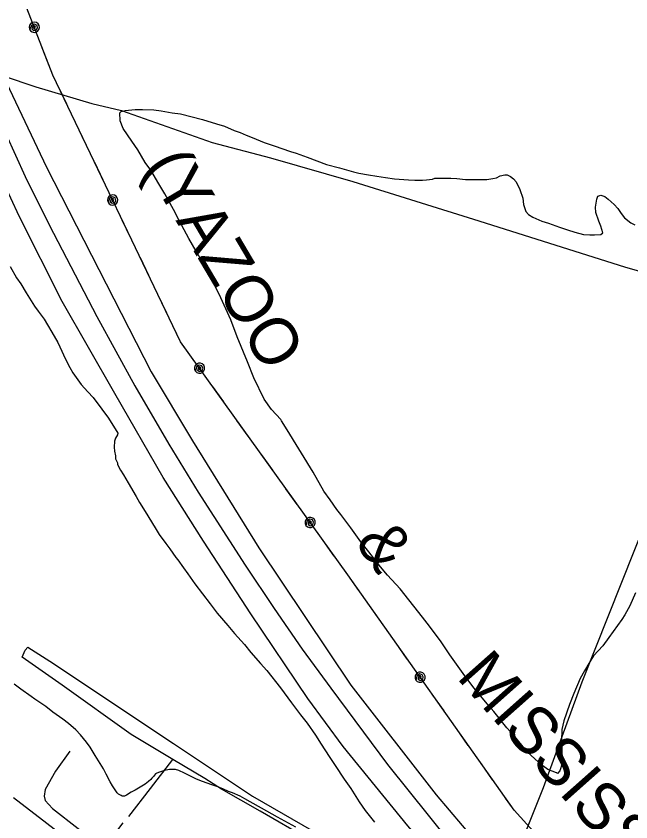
# Model space of a CAD drawing. Extents: x 3324104 to 3361979, y 612876 to 638273.
# Drawn here: x 3356671 to 3357754, y 633497 to 634915 of the extents above; entities that cross this region are included whole.
import ezdxf

# ---------------------------------------------------------------- set-up
doc = ezdxf.new("R2010")
doc.units = 0
for name, color, linetype in [('V-RAIL-IDEN', 7, 'Continuous'), ('V-RAIL-TRAK', 7, 'Continuous'), ('V-ROAD-CNTR', 7, 'Continuous'), ('V-SITE-VEGE', 7, 'Continuous'), ('V-TOPO-SHOR', 7, 'Continuous'), ('V-UTIL-LINE', 7, 'Continuous')]:
    doc.layers.add(name, color=color, linetype=linetype)

msp = doc.modelspace()

# ---------------------------------------------------------------- linework, layer by layer
at = {"layer": 'V-RAIL-TRAK'}
msp.add_lwpolyline([(3356215.6, 635761.2), (3356284.7, 635591.1), (3356397, 635315.7), (3356492.2, 635083.5), (3356560, 634919.7), (3356618.9, 634783), (3356687.5, 634633.1), (3356729.4, 634548), (3356813.2, 634386.8), (3356880.5, 634264.7), (3356940.4, 634162), (3356992, 634077.6), (3357074.6, 633949.1), (3357125.6, 633873), (3357175.2, 633801), (3357225.5, 633732.6), (3357325.5, 633598.4), (3357435.2, 633461.4), (3357535.9, 633341.2), (3357622.9, 633243.9), (3357692.7, 633167.7), (3357745.2, 633112.4), (3357828.1, 633029.8)], dxfattribs=at)
at = {"layer": 'V-ROAD-CNTR'}
msp.add_lwpolyline([(3356667, 633540.2), (3356968.1, 633308.6)], dxfattribs=at)
at = {"layer": 'V-SITE-VEGE'}
for points in [[(3356875, 634695.4), (3356860.1, 634717.2), (3356854.5, 634731.2), (3356854.1, 634745.2), (3356856.2, 634747.2), (3356863.4, 634749.3), (3356881, 634750.7), (3356893.9, 634750.6), (3356914.1, 634750), (3356926.5, 634748.3), (3356946.1, 634745.1), (3356960.6, 634743.5), (3356999.3, 634733.4), (3357024, 634725.5), (3357038, 634721.3), (3357055.5, 634713.9), (3357065.8, 634710.2), (3357076.1, 634706), (3357087, 634701.8), (3357108.1, 634692.9), (3357125.6, 634687.1), (3357154.5, 634677.1), (3357164.3, 634673.9), (3357183.9, 634667.1), (3357218, 634653.9), (3357240.7, 634648.1), (3357265.4, 634641.2), (3357274.7, 634639.1), (3357291.8, 634635.9), (3357306.2, 634633.7), (3357321.7, 634631.1), (3357337.7, 634628.9), (3357362, 634627.2), (3357373.4, 634626.6), (3357386.8, 634626.5), (3357394.1, 634627), (3357404.4, 634628.5), (3357408.6, 634630), (3357437, 634629.8), (3357447.3, 634629.2), (3357462.8, 634627.6), (3357492.8, 634627.4), (3357500, 634627.8), (3357510.4, 634629.3), (3357517.1, 634630.8), (3357523.4, 634633.9), (3357531.6, 634635.9), (3357535.8, 634635.9), (3357542, 634632.7), (3357547.1, 634629.1), (3357551.7, 634623.4), (3357558.4, 634609.9), (3357563.4, 634594.9), (3357564.9, 634583.5), (3357569, 634571.1), (3357573.6, 634565.9), (3357581.3, 634561.7), (3357596.8, 634554.3), (3357608.6, 634550.6), (3357628.2, 634543.8), (3357642.2, 634539.1), (3357655.1, 634534.8), (3357670, 634531.1), (3357681.4, 634530.5), (3357689.7, 634530.5), (3357700.5, 634530.9), (3357704.2, 634534), (3357702.6, 634539.7), (3357700.6, 634545.4), (3357697.1, 634554.2), (3357692, 634569.8), (3357691.5, 634579.1), (3357693.7, 634593), (3357695.8, 634598.2), (3357700.5, 634600.2), (3357707.7, 634597.6), (3357713.8, 634592.9), (3357724.1, 634583.5), (3357730.8, 634576.7), (3357736.4, 634567.9), (3357742.6, 634560.1), (3357753.4, 634551.3), (3357760.6, 634548.1)], [(3357761.6, 633900.4), (3357751.7, 633877.7), (3357742.8, 633861.7), (3357737.5, 633853.5), (3357714.6, 633821.6), (3357704.2, 633807.2), (3357688, 633789.7), (3357681.2, 633778.9), (3357671.8, 633762.9), (3357664.5, 633749.5), (3357653.5, 633723.2), (3357645.6, 633703.6), (3357635.6, 633675.3), (3357631.9, 633659.8), (3357631.8, 633640.1), (3357632.2, 633626.2), (3357632.6, 633605.5), (3357632.5, 633599.8), (3357628.8, 633586.9), (3357624.7, 633582.3), (3357622.6, 633583.3), (3357607.7, 633589.6), (3357598.9, 633595.9), (3357591.2, 633602.1), (3357577.3, 633614.6), (3357566.5, 633626.6), (3357549.1, 633647.4), (3357535.2, 633662.5), (3357512.7, 633691.6), (3357503.9, 633701.4), (3357477.8, 633732.6), (3357461.4, 633754.4), (3357435.2, 633791.3), (3357418.3, 633815.7), (3357394.8, 633846.9), (3357387.1, 633857.3), (3357347.6, 633907.1), (3357325.5, 633931.6), (3357312.7, 633946.1), (3357292.2, 633972.6), (3357278.3, 633990.3), (3357260.4, 634014.7), (3357255.3, 634021.5), (3357243, 634038.1), (3357235.8, 634046.9), (3357224, 634064.1), (3357213.2, 634079.1), (3357194.3, 634112.8), (3357148.3, 634187.1), (3357138.6, 634203.2), (3357137.5, 634205.2), (3357121.1, 634222.9), (3357108.3, 634241.1), (3357089.9, 634278.4), (3357078.7, 634306.9), (3357060.4, 634351), (3357049.2, 634380.5), (3357031.9, 634419.4), (3357019.7, 634444.8), (3357007.9, 634467.6), (3356988.5, 634501.4), (3356975.2, 634523.7), (3356958.8, 634554.3), (3356948.6, 634575), (3356933.3, 634602.5), (3356922.6, 634620.2), (3356908.8, 634644), (3356898.5, 634657.5), (3356885.7, 634679.9), (3356875, 634695.4)], [(3356661.1, 634474.5), (3356672.3, 634454.8), (3356679.5, 634443.9), (3356689.2, 634428.3), (3356694.8, 634419)], [(3356694.8, 634419), (3356703.5, 634405), (3356710.2, 634396.1), (3356720.5, 634382.1), (3356726.6, 634371.7), (3356734.3, 634359.3), (3356745, 634340.6), (3356751.6, 634325.6), (3356757.7, 634312.6), (3356765.9, 634297), (3356771.5, 634287.7), (3356780.3, 634275.2), (3356785.9, 634266.9), (3356797.7, 634253.9), (3356806.9, 634244), (3356822.3, 634223.8), (3356834.1, 634207.7), (3356850.5, 634181.2), (3356849.9, 634178.6), (3356846.3, 634172.5), (3356844.7, 634167.3), (3356844.1, 634156.4), (3356844.6, 634149.7), (3356846.1, 634141.4), (3356846.6, 634136.3), (3356849.6, 634129), (3356850.1, 634126.4), (3356855.2, 634116), (3356860.3, 634107.7), (3356868.5, 634093.7), (3356882.8, 634069.9), (3356888.5, 634059.5), (3356898.7, 634043.4), (3356916.1, 634014.8), (3356923.3, 634002.9), (3356935.1, 633987.3), (3356942.2, 633977.5), (3356952.5, 633962.4), (3356956.1, 633958.2), (3356966.3, 633944.2), (3356973.5, 633933.8), (3356986.3, 633916.2), (3357012.9, 633880.9), (3357025.2, 633864.8), (3357044.2, 633842.9), (3357056, 633828.9), (3357073.5, 633809.1), (3357084.8, 633795.1), (3357101.7, 633775.9), (3357112.5, 633763.9), (3357136.6, 633733.2), (3357156.1, 633706.8), (3357172, 633685.5), (3357183.8, 633670.9), (3357198.6, 633649.6), (3357208.3, 633634), (3357222.7, 633612.2), (3357232.9, 633596.2), (3357248.8, 633572.3), (3357260.6, 633556.2), (3357275.4, 633532.3), (3357285.6, 633517.2), (3357302.6, 633497)], [(3356999.6, 633568.2), (3356988.7, 633572.4), (3356968.1, 633582.9), (3356957.8, 633587.6), (3356952.1, 633589.2), (3356944.9, 633589.7), (3356941.3, 633589.7), (3356932.5, 633587.7), (3356923.7, 633584.7), (3356919, 633582.7), (3356916.9, 633581.6), (3356913.3, 633577), (3356910.2, 633573.9), (3356908.6, 633571.9), (3356904.5, 633568.3), (3356898.7, 633563.7), (3356881.1, 633552.9), (3356873.8, 633549.3), (3356865.5, 633544.2), (3356861.9, 633542.7), (3356858.3, 633542.7), (3356856.2, 633543.8), (3356851.6, 633545.9), (3356849.5, 633548.5), (3356841.3, 633560.4), (3356837.2, 633567.7), (3356830.1, 633581.2), (3356825, 633590.5), (3356816.3, 633604.5), (3356810.7, 633613.8), (3356802, 633628.9), (3356795.3, 633637.7), (3356784.5, 633650.7), (3356776.3, 633659), (3356763.5, 633670.5), (3356753.7, 633677.8), (3356736.2, 633690.3), (3356723.8, 633700.2), (3356704.3, 633713.3), (3356697.6, 633718), (3356679.6, 633731), (3356667.7, 633739.3)], [(3357164, 633488), (3357131.5, 633505.3), (3357113, 633516.3), (3357073.8, 633537.7), (3357066.1, 633542.4), (3357052.2, 633548.2), (3357045.5, 633550.8), (3357035.2, 633555.5), (3357026.4, 633559.2), (3357016.1, 633562.4), (3356999.6, 633568.2)]]:
    msp.add_lwpolyline(points, dxfattribs=at)
at = {"layer": 'V-TOPO-SHOR'}
msp.add_line((3357410.9, 633545), (3357538.8, 633394), dxfattribs=at)
for points in [[(3357488.8, 633340.8), (3357361, 633490.5), (3357247.1, 633629.7), (3357185, 633714.3), (3357084.4, 633863.2), (3357001, 633991), (3356930, 634103.5), (3356845.4, 634250.9), (3356752.5, 634412.9), (3356676.9, 634563), (3356602.8, 634721.4), (3356559.6, 634821.2), (3356583.3, 634831.5)], [(3356622.4, 634818.6), (3356648.7, 634809.9), (3356706.2, 634791), (3356804.8, 634761.2), (3356856.9, 634749), (3357016.6, 634693), (3357119.4, 634665.9), (3357263.9, 634623.9), (3357486.1, 634555), (3357744.4, 634473.3), (3357940.3, 634417.8), (3358017.4, 634397.2), (3358208.3, 634335.4), (3358442.4, 634272), (3358686.1, 634192.5), (3358914.6, 634128.4), (3359149.4, 634058.7)], [(3356648.7, 634809.9), (3356724.9, 634649.4), (3356909.1, 634289.2), (3356982.1, 634167.7), (3357098.5, 633979.7), (3357260.4, 633738), (3357410.9, 633545)], [(3357538.8, 633394), (3357555.5, 633446.2), (3357600.1, 633557.9), (3357668.1, 633743.9), (3357760.7, 633976.4), (3357840.6, 634175.6), (3357880.2, 634274.2), (3357940.3, 634417.8)], [(3357271.4, 633417.4), (3357100.8, 633515.9), (3357032.9, 633554.6), (3357003.8, 633573.6), (3356947.5, 633607.2), (3356874.2, 633651), (3356752.3, 633738), (3356682.3, 633787.2), (3356687.3, 633799.7), (3356692.2, 633804.5), (3356731, 633779.9), (3356948.5, 633635.2), (3357087.8, 633542.4), (3357314.5, 633411.6)], [(3356766.2, 633621.7), (3356740.9, 633586.4), (3356722.7, 633554.5), (3356720.5, 633542.6), (3356722.5, 633535), (3356735.7, 633521), (3356825.7, 633450.1), (3356860, 633495.8)], [(3356869.9, 633506.9), (3356907.7, 633556.1), (3356947.5, 633607.2)]]:
    msp.add_lwpolyline(points, dxfattribs=at)
at = {"layer": 'V-UTIL-LINE'}
for points in [[(3359778.1, 631804.5), (3358880.1, 632347.8), (3358382, 632698.4), (3357961.3, 633061.4), (3357548.2, 633517.7), (3357255.4, 633931.7), (3356960.8, 634342.1), (3356736.1, 634811.3), (3356526.7, 635349.8), (3356308.1, 635878.7), (3356075.3, 636434.9), (3356085, 636489.4)], [(3356703.4, 634895.6), (3356701.7, 634893.2), (3356704.1, 634893.2), (3356705.6, 634895.5), (3356704.2, 634898.1), (3356701, 634897.1), (3356699, 634892.8), (3356702, 634889.8), (3356706.9, 634890.3), (3356708.9, 634894.4), (3356708.3, 634898.8), (3356704, 634901.2), (3356698.8, 634899.5), (3356695, 634892.3), (3356696.9, 634889.3), (3356699.7, 634887.3), (3356703.2, 634886.6), (3356706.6, 634887.2), (3356709.6, 634889.1), (3356711.6, 634891.9), (3356712.4, 634895.4), (3356711.7, 634898.8), (3356709.9, 634901.8), (3356707, 634903.8), (3356703.6, 634904.6), (3356700.1, 634904), (3356697.1, 634902.1), (3356695.1, 634899.2), (3356694.4, 634895.8), (3356695, 634892.3)], [(3356729.8, 634827.5), (3356717.5, 634859.2)], [(3356760.6, 634760.3), (3356745.9, 634790.9)], [(3356792.5, 634693.5), (3356777.8, 634724.2)], [(3356824.5, 634626.8), (3356809.8, 634657.4)], [(3356841.3, 634591.6), (3356839.9, 634589.1), (3356842.2, 634589.3), (3356843.5, 634591.7), (3356842, 634594.2), (3356838.8, 634592.9), (3356837.2, 634588.5), (3356840.5, 634585.8), (3356845.2, 634586.7), (3356847, 634590.9), (3356846, 634595.2), (3356841.6, 634597.3), (3356836.5, 634595.2), (3356833.2, 634587.7), (3356835.3, 634584.9), (3356838.3, 634583.1), (3356841.8, 634582.6), (3356845.2, 634583.5), (3356848, 634585.6), (3356849.8, 634588.6), (3356850.3, 634592.1), (3356849.4, 634595.5), (3356847.3, 634598.3), (3356844.3, 634600.1), (3356840.8, 634600.6), (3356837.4, 634599.7), (3356834.6, 634597.6), (3356832.8, 634594.6), (3356832.3, 634591.1), (3356833.2, 634587.7)], [(3356872.9, 634525.8), (3356858.2, 634556.4)], [(3356904.8, 634459), (3356890.1, 634489.7)], [(3356936.8, 634392.3), (3356922.1, 634422.9)], [(3356971.5, 634327.2), (3356960.8, 634342.1), (3356954, 634356.2)], [(3356994.3, 634295.5), (3356993.3, 634292.8), (3356995.5, 634293.4), (3356996.4, 634296), (3356994.4, 634298.2), (3356991.6, 634296.3), (3356990.7, 634291.7), (3356994.4, 634289.6), (3356999, 634291.3), (3356999.9, 634295.8), (3356998.2, 634299.9), (3356993.5, 634301.1), (3356988.9, 634298.2), (3356986.9, 634290.3), (3356989.5, 634287.9), (3356992.8, 634286.6), (3356996.3, 634286.7), (3356999.5, 634288.2), (3357001.9, 634290.8), (3357003.1, 634294), (3357003, 634297.6), (3357001.6, 634300.8), (3356999, 634303.1), (3356995.7, 634304.4), (3356992.2, 634304.3), (3356989, 634302.8), (3356986.6, 634300.2), (3356985.4, 634297), (3356985.5, 634293.4), (3356986.9, 634290.3)], [(3357036.8, 634236.2), (3357017, 634263.8)], [(3357080, 634176.1), (3357060.2, 634203.7)], [(3357123.1, 634116), (3357103.3, 634143.6)], [(3357166.3, 634055.9), (3357146.5, 634083.5)], [(3357189, 634024.2), (3357188.1, 634021.5), (3357190.3, 634022.1), (3357191.2, 634024.7), (3357189.2, 634026.9), (3357186.4, 634025), (3357185.5, 634020.4), (3357189.2, 634018.3), (3357193.8, 634020), (3357194.7, 634024.5), (3357193, 634028.6), (3357188.3, 634029.8), (3357183.7, 634026.9), (3357181.7, 634018.9), (3357184.3, 634016.5), (3357187.6, 634015.3), (3357191.1, 634015.4), (3357194.3, 634016.9), (3357196.7, 634019.4), (3357197.9, 634022.7), (3357197.8, 634026.2), (3357196.4, 634029.4), (3357193.8, 634031.8), (3357190.5, 634033.1), (3357187, 634033), (3357183.8, 634031.5), (3357181.4, 634028.9), (3357180.2, 634025.6), (3357180.3, 634022.1), (3357181.7, 634018.9)], [(3357231.6, 633964.9), (3357211.8, 633992.5)], [(3357274.6, 633904.6), (3357255.4, 633931.7), (3357254.9, 633932.4)], [(3357317.3, 633844.2), (3357297.7, 633872)], [(3357360, 633783.8), (3357340.4, 633811.6)], [(3357382.5, 633752), (3357381.6, 633749.3), (3357383.8, 633749.9), (3357384.7, 633752.5), (3357382.7, 633754.6), (3357379.9, 633752.8), (3357379, 633748.2), (3357382.7, 633746.1), (3357387.2, 633747.7), (3357388.2, 633752.2), (3357386.5, 633756.3), (3357381.9, 633757.6), (3357377.2, 633754.7), (3357375.2, 633746.8), (3357377.7, 633744.3), (3357381, 633743.1), (3357384.5, 633743.2), (3357387.7, 633744.6), (3357390.2, 633747.2), (3357391.4, 633750.4), (3357391.3, 633753.9), (3357389.9, 633757.2), (3357387.3, 633759.6), (3357384.1, 633760.8), (3357380.6, 633760.7), (3357377.4, 633759.3), (3357374.9, 633756.8), (3357373.7, 633753.5), (3357373.8, 633750), (3357375.2, 633746.8)], [(3357424.7, 633692.4), (3357405.1, 633720.1)], [(3357467.4, 633631.9), (3357447.8, 633659.7)], [(3357510.1, 633571.5), (3357490.5, 633599.3)], [(3357553.6, 633511.7), (3357548.2, 633517.7), (3357533.2, 633538.9)]]:
    msp.add_lwpolyline(points, dxfattribs=at)

# ---------------------------------------------------------------- texts
at = {"layer": 'V-RAIL-IDEN'}
for s, rotation, p in [('(YAZOO', 300.5793, (3356895.2, 634651.3)), ('&', 306.3044, (3357266.3, 633989.2)), ('MISSISSIPPI', 311.5765, (3357445.1, 633751.4))]:
    msp.add_text(s, height=83, rotation=rotation, dxfattribs=at).set_placement(p)

doc.saveas('drawing.dxf')
